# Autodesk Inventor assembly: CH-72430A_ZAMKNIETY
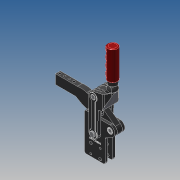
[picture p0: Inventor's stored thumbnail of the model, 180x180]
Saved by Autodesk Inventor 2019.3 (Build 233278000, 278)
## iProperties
Company: Î¢ÈíÖÐ¹ú
Created: 2012-10
Part Number: CH-72430A_ZAMKNIETY
Material: Ogólny
Description: STEP AP203
Document SubType Name: Assembly
Designer: CADENGINEERING4
Sending System: SolidWorks 2010
Preprocessor: SwSTEP 2.0
Title: CH-72430A.STEP
Author: Î¢ÈíÓÃ»§
Revision Number: ÈÎºÎ
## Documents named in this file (12)
- E:\CAD_CLAMPS\Heavy duty weldables\CH-72430A_DODAC\CH-72430A_ZAMKNIETY.iam
- E:\CAD_CLAMPS\Heavy duty weldables\CH-72430A_DODAC\72425-11.ipt
- E:\CAD_CLAMPS\Heavy duty weldables\CH-72430A_DODAC\72425-06.ipt
- E:\CAD_CLAMPS\Heavy duty weldables\CH-72430A_DODAC\72425-03.ipt
- E:\CAD_CLAMPS\Heavy duty weldables\CH-72430A_DODAC\72425-09.ipt
- E:\CAD_CLAMPS\Heavy duty weldables\CH-72430A_DODAC\M12.ipt
- E:\CAD_CLAMPS\Heavy duty weldables\CH-72430A_DODAC\72425-10.ipt
- E:\CAD_CLAMPS\Heavy duty weldables\CH-72430A_DODAC\72425-08.ipt
- E:\CAD_CLAMPS\Heavy duty weldables\CH-72430A_DODAC\72425-04.ipt
- E:\CAD_CLAMPS\Heavy duty weldables\CH-72430A_DODAC\CH-72430A-02.ipt
- E:\CAD_CLAMPS\Heavy duty weldables\CH-72430A_DODAC\CH-72430A-01.ipt
- E:\CAD_CLAMPS\Heavy duty weldables\CH-72430A_DODAC\72425-07.ipt
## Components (20 placed, 20 different names)
1. 72425-11_1 — Zestawiające:1, Zestawiające:2, Kątowe:1
2. 72425-06_2 — Zestawiające:16, Równoległe:5
3. 72425-03_3 — Zestawiające:3, Zestawiające:5, Zestawiające:19, Zestawiające:20, Zestawiające:22, Równoległe:8
4. 72425-09_4
5. 72425-06_5 — Zestawiające:10, Zestawiające:13, Zestawiające:18, Równoległe:7
6. M12_6
7. 72425-06_7 — Zestawiające:3, Zestawiające:6, Zestawiające:7, Równoległe:8
8. 72425-10_8 — Zestawiające:25
9. 72425-06_9 — Zestawiające:11, Zestawiające:12
10. 72425-06_10 — Zestawiające:15, Równoległe:4, Zestawiające:17, Równoległe:6
11. 72425-06_11
12. 72425-06_12
13. 72425-08_13 — Zestawiające:18, Równoległe:7, Zestawiające:19
14. 72425-08_14 — Zestawiające:17, Równoległe:6, Zestawiające:24
15. 72425-03_15 — Zestawiające:4, Równoległe:2, Zestawiające:5, Zestawiające:21
16. 72425-04_16 — Zestawiające:1, Zestawiające:2, Kątowe:1, Zestawiające:7, Zestawiające:14, Równoległe:3, Zestawiające:20, Zestawiające:21, Zestawiające:25
17. 72425-06_17 — Zestawiające:4, Równoległe:2, Zestawiające:6
18. CH-72430A-02_18 — Zestawiające:10, Zestawiające:11, Zestawiające:12, Zestawiające:13, Zestawiające:22, Zestawiające:23, Zestawiające:24, Kątowe:2
19. CH-72430A-01_19 — Zestawiające:15, Zestawiające:16, Równoległe:4, Równoległe:5, Zestawiające:23, Kątowe:2
20. 72425-07_20 — Zestawiające:14, Równoległe:3
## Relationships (32: Mate 23, Flush 7, Angle 2)
- Zestawiające:1 [Mate]: 72425-11_1 ↔ 72425-04_16
- Zestawiające:2 [Mate]: 72425-11_1 ↔ 72425-04_16
- Kątowe:1 [Angle]: 72425-11_1 ↔ 72425-04_16
- Zestawiające:3 [Mate]: 72425-03_3 ↔ 72425-06_7
- Zestawiające:4 [Mate]: 72425-03_15 ↔ 72425-06_17
- Równoległe:2 [Flush]: 72425-03_15 ↔ 72425-06_17
- Zestawiające:5 [Mate]: 72425-03_3 ↔ 72425-03_15
- Zestawiające:6 [Mate]: 72425-06_7 ↔ 72425-06_17
- Zestawiające:7 [Mate]: 72425-06_7 ↔ 72425-04_16
- Zestawiające:10 [Mate]: 72425-06_5 ↔ CH-72430A-02_18
- Zestawiające:11 [Mate]: 72425-06_9 ↔ CH-72430A-02_18
- Zestawiające:12 [Mate]: 72425-06_9 ↔ CH-72430A-02_18
- Zestawiające:13 [Mate]: 72425-06_5 ↔ CH-72430A-02_18
- Zestawiające:14 [Mate]: 72425-04_16 ↔ 72425-07_20
- Równoległe:3 [Flush]: 72425-04_16 ↔ 72425-07_20
- Zestawiające:15 [Mate]: 72425-06_10 ↔ CH-72430A-01_19
- Zestawiające:16 [Mate]: 72425-06_2 ↔ CH-72430A-01_19
- Równoległe:4 [Flush]: 72425-06_10 ↔ CH-72430A-01_19
- Równoległe:5 [Flush]: 72425-06_2 ↔ CH-72430A-01_19
- Zestawiające:17 [Mate]: 72425-06_10 ↔ 72425-08_14
- Równoległe:6 [Flush]: 72425-06_10 ↔ 72425-08_14
- Zestawiające:18 [Mate]: 72425-06_5 ↔ 72425-08_13
- Równoległe:7 [Flush]: 72425-06_5 ↔ 72425-08_13
- Zestawiające:19 [Mate]: 72425-03_3 ↔ 72425-08_13
- Zestawiające:20 [Mate]: 72425-03_3 ↔ 72425-04_16
- Zestawiające:21 [Mate]: 72425-03_15 ↔ 72425-04_16
- Zestawiające:22 [Mate]: 72425-03_3 ↔ CH-72430A-02_18
- Równoległe:8 [Flush]: 72425-03_3 ↔ 72425-06_7
- Zestawiające:23 [Mate]: CH-72430A-02_18 ↔ CH-72430A-01_19
- Zestawiające:24 [Mate]: 72425-08_14 ↔ CH-72430A-02_18
- Zestawiające:25 [Mate]: 72425-10_8 ↔ 72425-04_16
- Kątowe:2 [Angle]: CH-72430A-02_18 ↔ CH-72430A-01_19
